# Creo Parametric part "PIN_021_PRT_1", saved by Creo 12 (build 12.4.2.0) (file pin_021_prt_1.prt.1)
Units: Custom; MM, KILOGRAM, SECS

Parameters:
  PTC_WM_ITERATION = "0"
  PTC_WM_VERSION = "-.0"
  PTC_WM_LIFECYCLE_STATE = "In Work"
  PTC_WM_LIFECYCLE = "MO_CADDocument"
  PTC_WM_CREATED_BY = "Maximilian Roepper (Z0017RMS: MO)"
  PTC_WM_CREATED_ON = "18-Sep-26 11:36:42 AM"
  PTC_WM_MODIFIED_BY = "Maximilian Roepper (Z0017RMS: MO)"
  PTC_WM_MODIFIED_ON = "18-Sep-26 11:36:46 AM"
  PDMLINKNUMBER = "PDM000071454992"
  PTC_WM_NAME = "pin_021_prt_1.prt"
  PTC_WM_NUMBER = "PDM000071454992"

Other parameters: WEIGHT, WEIGHT_FACTOR, WEIGHT_ADD, _MASS_TEMP, _DIFF_TEMP, MC_ERRORS, SUPPLIER

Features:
  1. coordinate system
  2. datum plane "PRT_YZ"
  3. datum plane "PRT_XY"
  4. datum plane "PRT_XZ"
  5. coordinate system
  6. datum axis
  7. datum axis
  8. datum axis
  9. coordinate system
  10. imported feature
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
Other named items: PRT, SIEMENS_MO, DRW_VIEW_ORG, PRT_X, PRT_Y, PRT_Z, CS0, ROUGH_GROB

Layers: 00_STD_CSYS-KSYS, 01_STD_PLANES-EBENEN, 02_STD_AXES-ACHSEN, 03_STD_CSYS-KSYS, 24_IMPORT_FEAT-IMPORT_KE

Surfaces: 9 plane, 1 cylinder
